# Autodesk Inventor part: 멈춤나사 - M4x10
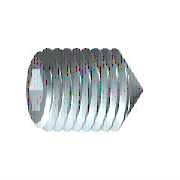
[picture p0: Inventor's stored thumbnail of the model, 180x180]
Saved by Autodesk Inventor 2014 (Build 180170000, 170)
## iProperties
Created: 2012-02
Part Number: 멈춤나사 - M4x10
Material: 강철, 연강
Description: 6각 소켓 머리 없는 멈춤 나사
Document SubType Name: Modeling
Standard: KS B 1028
Designer: mduedu
Standards Organization: KS
Language: ko-KR
Size Designation: 원추점 M4x10
Categories: <MemberInstance><Categories><Category DisplayName="조임쇠" InternalName="e4da775c-781d-43d5-af7c-5136215cf5a6" Mnemonic="FSTN"><Category DisplayName="볼트" InternalN
Density: 7.86 g/cm^3
Mass: 0.792069 g
Surface Area: 1.48192 cm^2
Volume: 0.100772 cm^3
Appearance: 강철
Author: mduedu
IsCustomPart: 1
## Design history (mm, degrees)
sketch "스케치1"
  geometry: L1 (0, 0)-(6.833, 0); L2 (10, 1.155)-(10, 2); L3 (10, 2)-(0, 2); L4 (10, 1.155)-(7.5, 1.155); L5 (7.5, 1.155)-(6.833, 0); L6 (0, -0.4)-(0, 2.4) reference; L7 (0, 2)-(0, 0)
  constraints: 13 end point, 3 parallel, 1 collinear, 1 perpendicular, 1 point on line
  dimensions: "d0" = 2.5 distance of L2.start L4.end (= INTI); "d1" = 60 deg angle of L5 L1; "d2" = 4 diameter of L3 L1 (= NND); "d3" = 2.3094 diameter of L4 L1 (= 1.1547 x SW); "d5" = 10 distance from line of L2 L3.end (= NLG)
revolve "본체" sketch "스케치1" stored, may be unused: angle "d6" = 90 deg
sketch "스케치2"
  geometry: L1 (-0.577, 1)-(0.577, 1); L2 (0.577, 1)-(1.155, 0); L3 (1.155, 0)-(0.577, -1); L4 (0.577, -1)-(-0.577, -1); L5 (-0.577, -1)-(-1.155, 0); L6 (-1.155, 0)-(-0.577, 1); 3 further points
  constraints: 12 end point, 1 coincident, 1 horizontal, 13 other
extrude "슬롯" join sketch "스케치2" taper "d7" = 0 deg; stored distance "d21" = 10
workaxis "Work Axis1"
workplane "Work Plane1"
sketch "스케치4"
  geometry: L1 (-5, 0.2)-(-3.2, 2) reference; L2 (-5, -0.2)-(-3.2, -2) reference; L3 (-3.2, 2)-(-5.2, 0); L4 (-3.2, -2)-(-5.2, 0); 2 further points
  constraints: 4 end point, 2 collinear, 1 coincident
body "Solid1"
feature "스레드" dims "d12" = 10 (= NLG), "d13" = 0
chamfer "모따기1" distance "d8" = 1.8 (computed from NND, SPD, FAWI); stored, may be unused: angle "d9" = 45 deg (= FAWI), second distance "d34" = 1.8 (computed from NND, SPD, FAWI)
chamfer "모따기2" distance "d10" = 0.42941 (= -0.5 x GD1 + 0.5 x NND); stored, may be unused: angle "d11" = 45 deg (= FAWI), second distance "d35" = 0.42941 (= -0.5 x GD1 + 0.5 x NND)
other parameters: "NND" = 4 [user parameter; used in 5 equation terms], "NLG" = 10 [user parameter; used in 2 equation terms], "INTI" = 2.5 [user parameter; used in 1 equation term], "FAWI" = 45 deg [user parameter; used in 4 equation terms], "SW" = 2 [user parameter; used in 2 equation terms], "GD1" = 3.14117 (= THREADDIA - 1.2269 x PTC) [user parameter; used in 2 equation terms], "d4" = 0, "FAWI1" = 45 deg [user parameter], "SPD" = 0.4 [user parameter; used in 2 equation terms], "d36" = 0, "d37" = 0, "GUL" = 0.42941 (= 0.61345 x PTC) [user parameter], "TPU" = 14.28571 (computed from PTC) [user parameter], "TOA" = 30 deg [user parameter], "THREADDIA" = 4 [user parameter; used in 1 equation term], "PTC" = 0.7 [user parameter; used in 4 equation terms], "GAL" = 0.42941 (= 0.61345 x PTC) [user parameter], "E0" = 2.31 (= 1.155 x SW) [user parameter]
